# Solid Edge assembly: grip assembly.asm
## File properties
Author: nakano
Template: iso metric assembly.asm
Last saved by: nakano
Revision: 6
Application: Solid Edge
Username: nakano
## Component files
asb-09.par
hitec hs-422.asm
Spirol INS 20-M3-.226.par
gripper finger pad.par
gripper wheel.par
gripper arm.par
gripper finger right.par
gripper wrist.par
gripper finger left.par
lga-kt.par
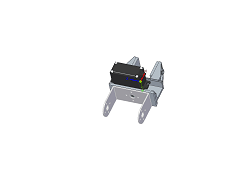
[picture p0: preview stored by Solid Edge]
